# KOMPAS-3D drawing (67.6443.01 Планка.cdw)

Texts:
  Планка
  *Размер для справок.
  Кромки А и Б заострить.
  Шероховатость поверхностей реза  6,3 .
  Нач. КО
Dimensions and other numbers on the sheet: 290; 8; 83; 55; 12; 85; 125; 7; 4; 38; 11; 45; 5,5; 4 отв.; 1:1; 1; 0,316; 0; 2; 3; 5; 6; 9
